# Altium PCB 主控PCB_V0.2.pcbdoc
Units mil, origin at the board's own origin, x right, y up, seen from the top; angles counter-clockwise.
Board outline 2286.79 x 1620 mil, 2 copper layers (Top Layer, Bottom Layer); 44 components, 39 nets, 171 pads, 174 vias.
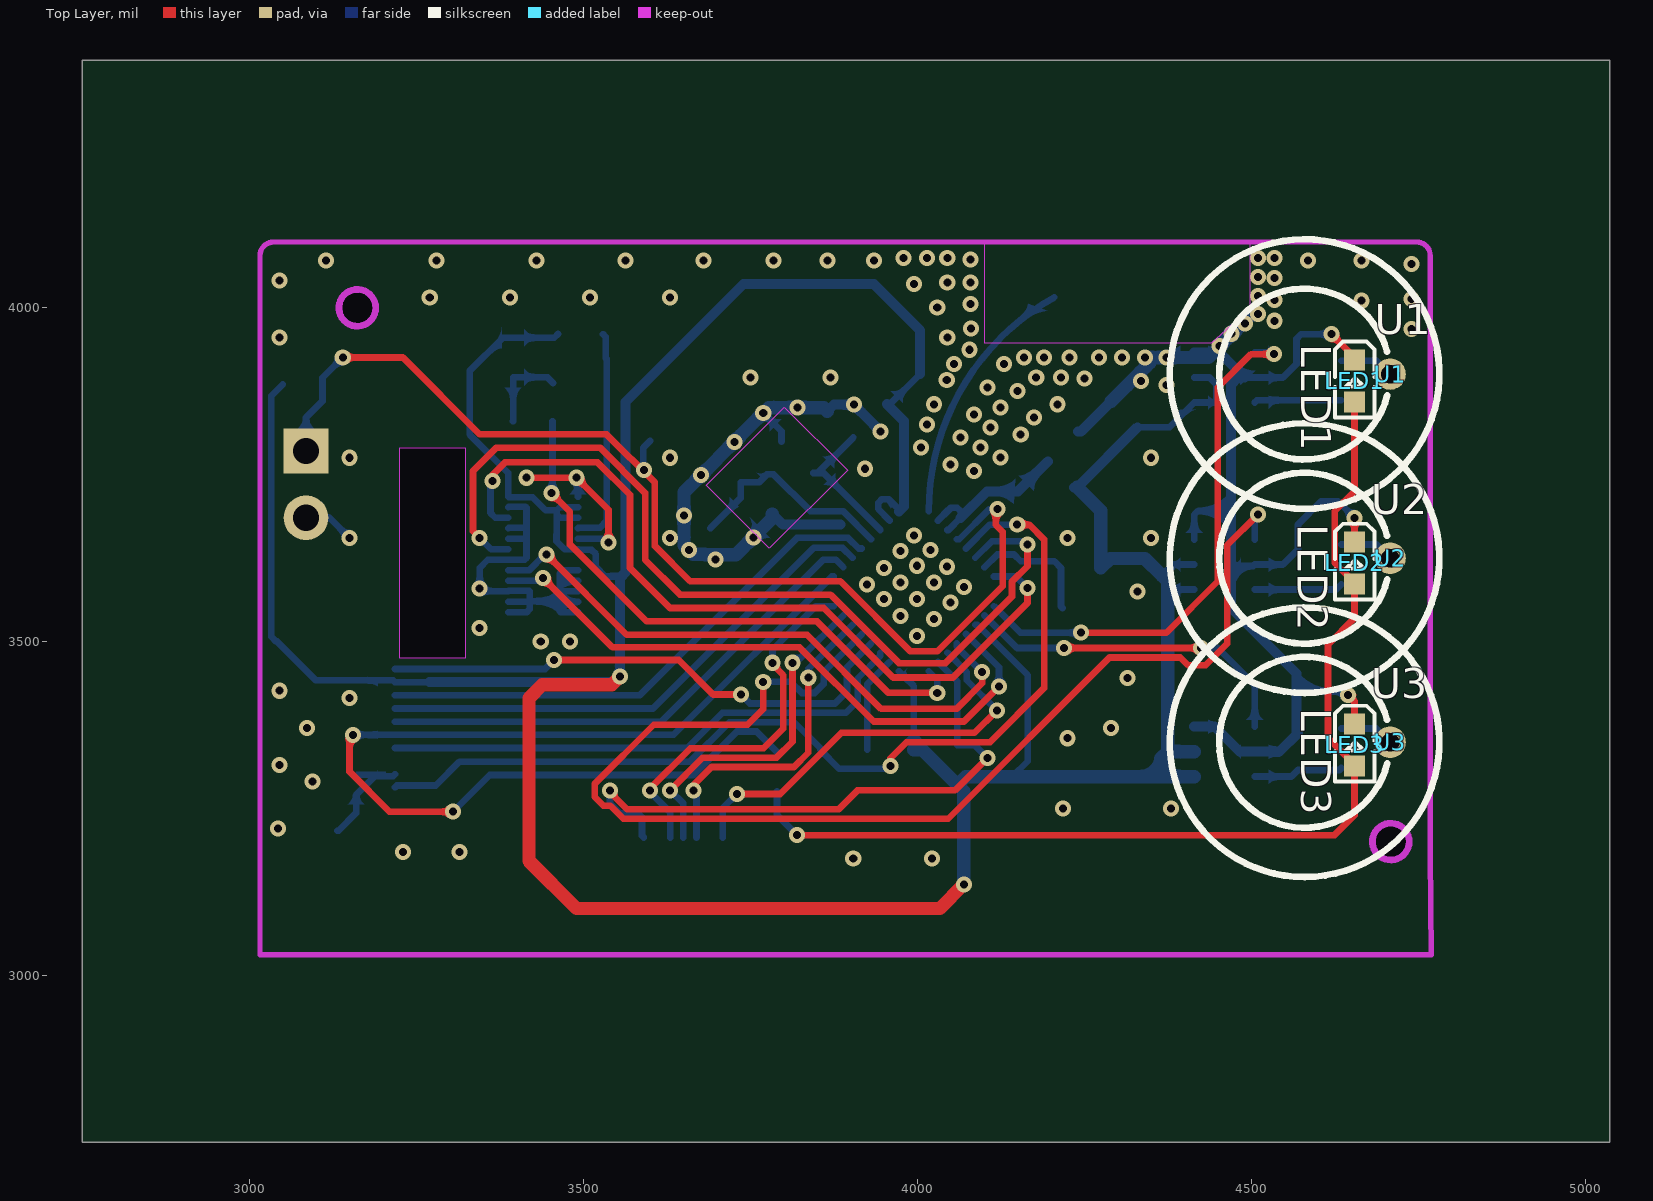
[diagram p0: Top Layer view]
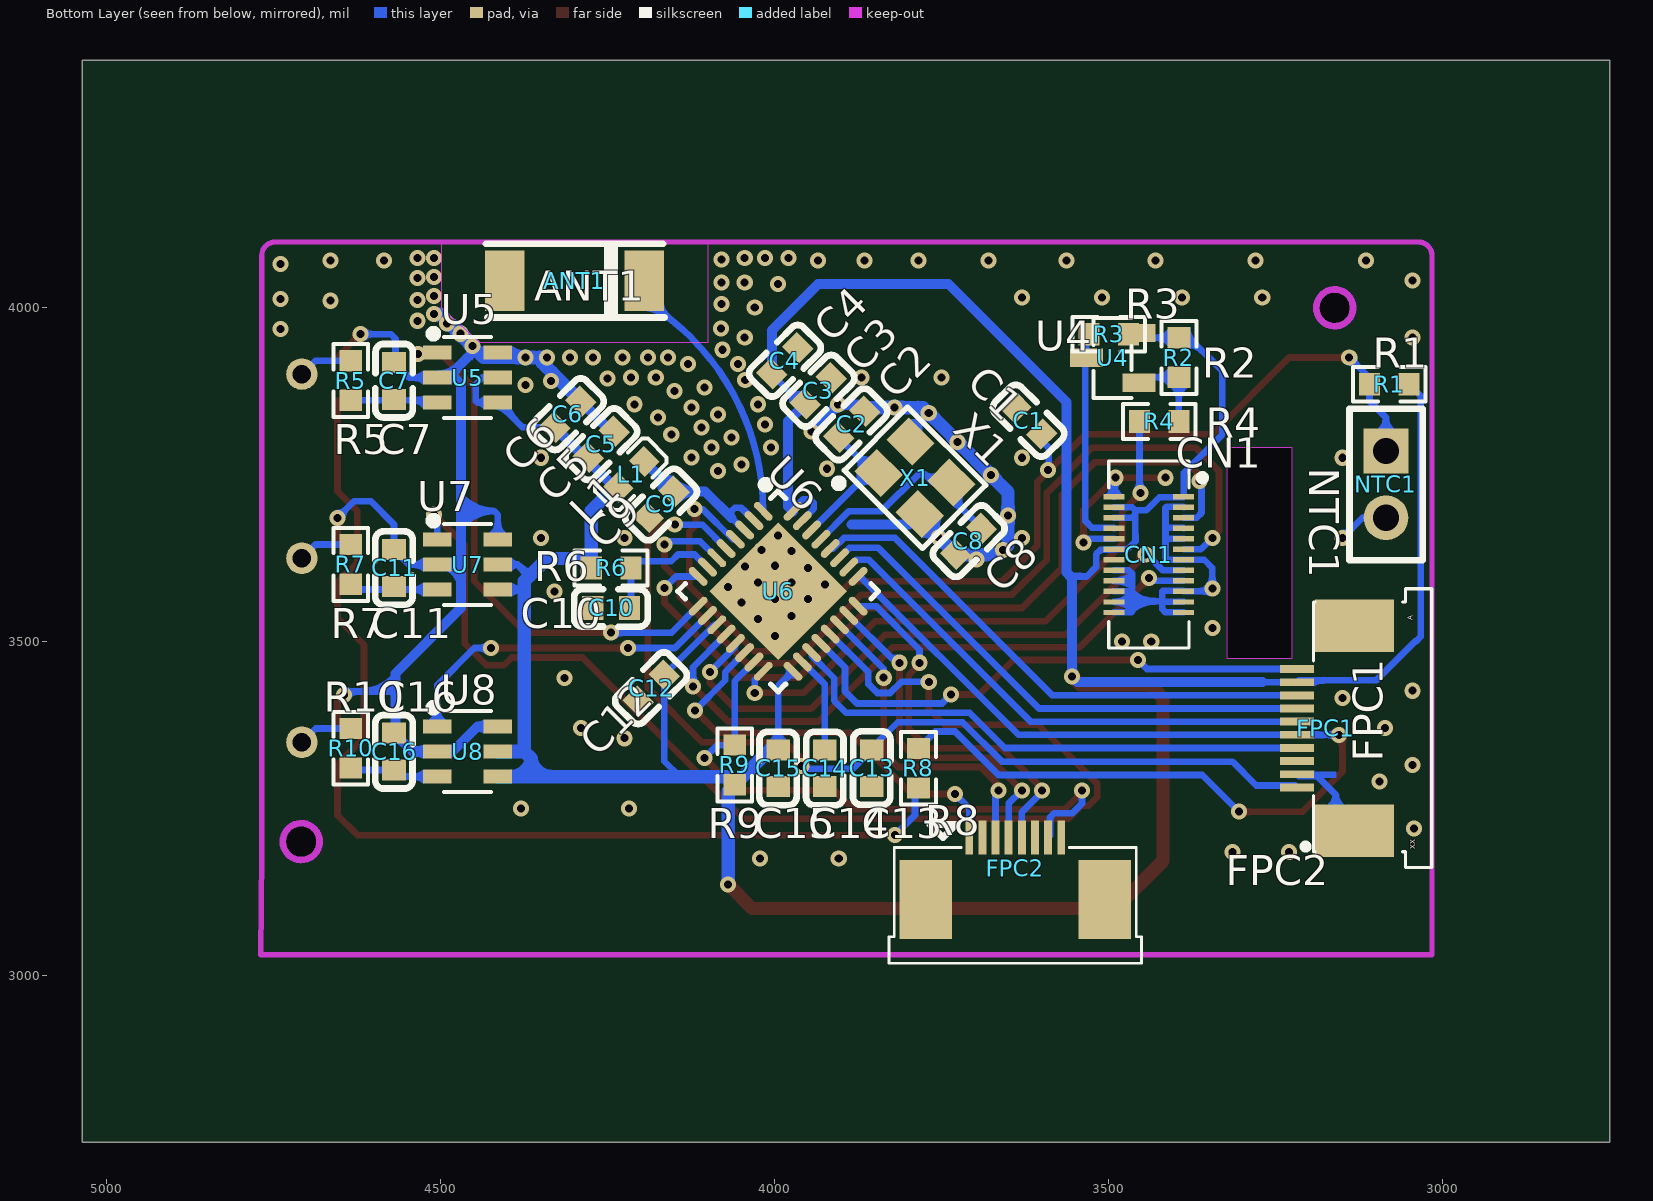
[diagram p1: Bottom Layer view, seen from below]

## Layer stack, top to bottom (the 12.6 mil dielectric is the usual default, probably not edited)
Top Layer: signal copper (thickness not stored)
Dielectric: dielectric 12.6, FR-4, Dk 4.8
Bottom Layer: signal copper (thickness not stored)

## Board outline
5036.79,2750 2750,2750 2750,4370 5036.79,4370
cut-out: 4736.57,3200.19 ccw(c4709.02,3199.82) 4681.46,3200.19 ccw(c4709.02,3200.56)
cut-out: 3189.33,3999.4 ccw(c3161.77,3999.4) 3134.21,3999.4 ccw(c3161.77,3999.4)
cut-out: 3225,3790 3323.43,3790 3323.43,3475.04 3225,3475.04

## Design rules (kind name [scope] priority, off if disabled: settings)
BoardOutlineClearance copperThickness1oz [All] p0: genericclearance=10 ignorepadtopadclearanceinfootprint=FALSE except(0: Arc-SplitContinuation Track-SplitContinuation SMDPad-SplitContinuation THPad-SplitContinuation Via-SplitContinuation Fill-SplitContinuation Poly-SplitContinuation Region-SplitContinuation Text-SplitContinuation; 6: Track-CutoutEdge SMDPad-CutoutEdge THPad-CutoutEdge Via-CutoutEdge Region-CutoutEdge; 11.8: Track-OutlineEdge SMDPad-OutlineEdge THPad-OutlineEdge Via-OutlineEdge Fill-OutlineEdge Region-OutlineEdge Poly-OutlineEdge Text-OutlineEdge Fill-CutoutEdge)
BoardOutlineClearance copperThickness2oz [All] p0: genericclearance=10 ignorepadtopadclearanceinfootprint=FALSE except(0: Arc-SplitContinuation Track-SplitContinuation SMDPad-SplitContinuation THPad-SplitContinuation Via-SplitContinuation Fill-SplitContinuation Poly-SplitContinuation Region-SplitContinuation Text-SplitContinuation; 6: Track-CutoutEdge SMDPad-CutoutEdge THPad-CutoutEdge Via-CutoutEdge Region-CutoutEdge; 11.8: Track-OutlineEdge SMDPad-OutlineEdge THPad-OutlineEdge Via-OutlineEdge Fill-OutlineEdge Region-OutlineEdge Poly-OutlineEdge Text-OutlineEdge Fill-CutoutEdge)
Clearance copperThickness1oz [(InNet('$1N1219') OR InNet('GND') OR InNet('3V3') OR InNet('$1N1185') OR InNet('$1N1981') OR InNet('$1N1223') OR InNet('$1N1184') OR InNet('CHIP_EN') OR InNet('VDD_SPI') OR InNet('$1N1977') OR InNet('$1N1980') OR InNet('GPIO0') OR InNet('GPIO6') OR InNet('GPIO7') OR InNet('GPIO2') OR InNet('K') OR InNet('GPIO3') OR InNet('ADC_VIN') OR InNet('ESP_TX') OR InNet('ESP_RX') OR InNet('GPIO13') OR InNet('GPIO12') OR InNet('DN1') OR InNet('DP1') OR InNet('$1N3691') OR InNet('$1N1982') OR InNet('$1N1983') OR InNet('$1N1984') OR InNet('GPIO9') OR InNet('$1N1544') OR InNet('BL') OR InNet('GPIO4') OR InNet('GPIO5') OR InNet('$1N7080') OR InNet('GPIO8') OR InNet('GPIO14') OR InNet('GPIO15') OR InNet('GPIO16') OR InNet('GPIO17'))] p1: gap=7 ignorepadtopadclearanceinfootprint=FALSE except(4: Track-Track; 6: Track-SMDPad SMDPad-SMDPad Track-THPad SMDPad-THPad THPad-THPad Track-Via SMDPad-Via THPad-Via Via-Via SMDPad-Fill THPad-Fill Via-Fill Fill-Fill Track-Region SMDPad-Region THPad-Region Via-Region Region-Region Track-Poly SMDPad-Poly THPad-Poly Via-Poly Fill-Poly Region-Poly Poly-Poly Track-Text SMDPad-Text THPad-Text Via-Text Fill-Text Region-Text Poly-Text Text-Text; 6.9: Track-Hole SMDPad-Hole THPad-Hole Via-Hole Fill-Hole Region-Hole Poly-Hole Text-Hole Sheet-Hole; 11.8: Track-Fill Fill-Region Track-Sheet SMDPad-Sheet THPad-Sheet Via-Sheet Fill-Sheet Region-Sheet Poly-Sheet Text-Sheet)
Clearance copperThickness2oz [All] p1: gap=7 ignorepadtopadclearanceinfootprint=FALSE except(6: Track-SMDPad SMDPad-SMDPad Track-THPad SMDPad-THPad THPad-THPad Track-Via SMDPad-Via THPad-Via Via-Via SMDPad-Fill THPad-Fill Via-Fill Fill-Fill Track-Region SMDPad-Region THPad-Region Via-Region Region-Region Track-Poly SMDPad-Poly THPad-Poly Via-Poly Fill-Poly Region-Poly Poly-Poly Track-Text SMDPad-Text THPad-Text Via-Text Fill-Text Region-Text Poly-Text Text-Text; 6.9: Track-Hole SMDPad-Hole THPad-Hole Via-Hole Fill-Hole Region-Hole Poly-Hole Text-Hole Sheet-Hole; 8: Track-Track; 11.8: Track-Fill Fill-Region Track-Sheet SMDPad-Sheet THPad-Sheet Via-Sheet Fill-Sheet Region-Sheet Poly-Sheet Text-Sheet)
DiffPairsRouting differentialPair [All] p1: maxuncoupledlength=10 minlimit=6 maxlimit=6 mostfreqgap=6 toplayer_minwidth=5 toplayer_prefwidth=10 toplayer_maxwidth=100 bottomlayer_minwidth=5 bottomlayer_prefwidth=10 bottomlayer_maxwidth=100
PasteMaskExpansion pasteMaskExpansion [All] p1: expansion=0
PlaneConnect innerPlane [All] p1: planeconnectstyle=Relief reliefexpansion=20 reliefentries=4 reliefconductorwidth=10 reliefairgap=10
PolygonConnect copperRegion [All] p1: connectstyle=Relief reliefentries=4 reliefconductorwidth=10 polygonreliefangle="90 Angle" airgapwidth=10
RoutingVias viaSize [All] p1: viastyle="Through Hole" holewidth=12.0078 minholewidth=11.811 maxholewidth=248.0314 width=24.0158 minwidth=19.685 maxwidth=393.7008
SolderMaskExpansion solderMaskExpansion [All] p1: useseparateexpansions=TRUE expansion=2 expansionbottom=2
Width copperThickness1oz [All] p1: maxlimit=100 minlimit=5 preferedwidth=10
Width copperThickness2oz [All] p1: maxlimit=100 minlimit=8 preferedwidth=10

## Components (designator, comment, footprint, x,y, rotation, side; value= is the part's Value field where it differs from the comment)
ANT1 "CA-C03" ANT-SMD_CA-C03 4300,4040 r180 bottom
C1 "CGA0603X7R104K500JT" C0603 3620,3830 r225 bottom
C2 "CC0603KRNPO9BN100" C0603 3885,3825 r135 bottom
C3 "CC0603KRX7R9BB104" C0603 3935,3875 r315 bottom
C4 "CL10A106KP8NNNC" C0603 3985,3920 r315 bottom
C5 "CL10A105KA8NNNC" C0603 4260,3795 r315 bottom
C6 "CL10A106KP8NNNC" C0603 4310,3840 r315 bottom
C7 "CC0603JRNPO9BN150" C0603 4570,3890 r270 bottom
C8 "CC0603FRNPO9BN100" C0603 3710,3650 r315 bottom
C9 "CC0603KRX7R9BB104" C0603 4170,3705 r135 bottom
C10 "CL10A105KA8NNNC" C0603 4245,3550 r180 bottom
C11 "CC0603JRNPO9BN150" C0603 4570,3610 r90 bottom
C12 "CC0603KRX7R9BB104" C0603 4185,3430 r135 bottom
C13 "CGA0603X7R104K500JT" C0603 3855,3310 r270 bottom
C14 "CL10A106KP8NNNC" C0603 3925,3310 r90 bottom
C15 "CC0603KRX7R9BB104" C0603 3995,3310 r90 bottom
C16 "CC0603JRNPO9BN150" C0603 4570,3335 r90 bottom
CN1 "DF37NC-24DS-0.4V(51)" CONN-SMD_DF37NC-24DS-0.4V-51 3440,3630 r270 bottom locked
FPC1 "F0501-T-10-20T-R" FPC-SMD_F0501-T-10-20T-R 3175,3370 r90 bottom locked
FPC2 "F0501-T-08-20T-R" FPC-SMD_8P-P0.50_L4.4-W9.6 3640,3160 r180 bottom
L1 "SDCL1608C2N0STDF" l0603 4215,3750 r135 bottom
LED1 "LTST-C193TBKT-5A" LED0603-RD 4655,3890 r270 top
LED2 "LTST-C193TBKT-5A" LED0603-RD 4655,3617.5 r270 top
LED3 "LTST-C193TBKT-5A" LED0603-RD 4655,3345 r270 top
NTC1 "HDR-F_2.54_1x2P" HDR-TH_2P-P2.54-V-F 3085,3735 r270 bottom
R1 "0603WAF1002T5E" R0603 3080,3885 r180 bottom
R2 "Res_0402" R0603 3395,3925 r270 bottom
R3 "Res_0402" R0603 3500,3960 r0 bottom
R4 "0603WAF1001T5E" R0603 3424.33,3829.34 r180 bottom
R5 "0603WAF1001T5E" R0603 4635,3890.56 r270 bottom
R6 "0603WAF1002T5E" R0603 4245,3610 r180 bottom
R7 "0603WAF1001T5E" R0603 4635,3615.28 r270 bottom
R8 "0603WAF3300T5E" R0603 3785,3310 r270 bottom
R9 "0603WAF1002T5E" R0603 4060,3315 r90 bottom
R10 "0603WAF1001T5E" R0603 4635,3340 r270 bottom
U1 "F10-10-6.5-0.4P" TH_F10-10-6.5-0.4P 4707.91,3900.16 r0 top
U2 "F10-10-6.5-0.4P" TH_F10-10-6.5-0.4P 4707.91,3624.57 r0 top
U3 "F10-10-6.5-0.4P" TH_F10-10-6.5-0.4P 4707.91,3348.98 r0 top
U4 "AO3401_1" SOT-23-3_L2.9-W1.3-P1.90-LS2.4-BR 3494.2,3924.34 r180 bottom
U5 "JL423B" SOT-23-6_L2.9-W1.6-P0.95-LS2.8-BL-2 4460,3895 r270 bottom
U6 "ESP32-C3FN4" QFN-32_L5.0-W5.0-P0.50-BL-EP3.7 3995,3575 r315 bottom locked
U7 "JL423B" SOT-23-6_L2.9-W1.6-P0.95-LS2.8-BL-2 4460,3615 r270 bottom
U8 "JL423B" SOT-23-6_L2.9-W1.6-P0.95-LS2.8-BL-2 4460,3335 r270 bottom
X1 "X322540MPB4SI" OSC-SMD_4P-L3.2-W2.5-BL_SIT8008BI 3790,3745 r225 bottom

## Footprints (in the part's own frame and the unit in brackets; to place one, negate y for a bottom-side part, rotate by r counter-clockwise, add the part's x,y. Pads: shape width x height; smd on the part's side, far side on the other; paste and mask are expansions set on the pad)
ANT-SMD_CA-C03 [mm]
  rect 1.5x2.3 smd: 1(-2.65,0) 2(2.65,0)
  silkscreen extent -3.37,-1.4 3.43,1.4
C0603 [mm]
  rect 0.8x0.9 smd: 1(-0.7,0) 2(0.7,0)
  silkscreen extent -1.41,-0.71 1.39,0.72
CONN-SMD_DF37NC-24DS-0.4V-51 [mm]
  rect 0.2x0.8 smd: 1(-2.2,1.325) 2(-2.2,-1.325) 3(-1.8,1.325) 4(-1.8,-1.325) 5(-1.4,1.325) 6(-1.4,-1.325) 7(-1,1.325) 8(-1,-1.325) 9(-0.6,1.325) 10(-0.6,-1.325) 11(-0.2,1.325) 12(-0.2,-1.325) 13(0.2,1.325) 14(0.2,-1.325) 15(0.6,1.325) 16(0.6,-1.325) 17(1,1.325) 18(1,-1.325) 19(1.4,1.325) 20(1.4,-1.325) 21(1.8,1.325) 22(1.8,-1.325) 23(2.2,1.325) 24(2.2,-1.325)
  silkscreen extent -3.56,-1.52 3.56,2.16
FPC-SMD_8P-P0.50_L4.4-W9.6 [mm]
  rect 2x3 smd: 0(-3.4,-1.175) 0(3.4,-1.175)
  rect 0.3x1.3 smd: 1(-1.75,1.175) 2(-1.25,1.175) 3(-0.75,1.175) 4(-0.25,1.175) 5(0.25,1.175) 6(0.75,1.175) 7(1.25,1.175) 8(1.75,1.175)
  silkscreen extent -4.8,-3.6 4.8,1.68
FPC-SMD_F0501-T-10-20T-R [mm]
  rect 0.3x1.3 smd: 1(-2.25,1.097) 2(-1.75,1.097) 3(-1.25,1.097) 4(-0.75,1.097) 5(-0.25,1.097) 6(0.25,1.097) 7(0.75,1.097) 8(1.25,1.097) 9(1.75,1.097) 10(2.25,1.097)
  rect 2x3 smd: 11(3.9,-1.097) 12(-3.9,-1.097)
  silkscreen extent -5.3,-4.03 5.3,0.87
HDR-TH_2P-P2.54-V-F [mm]
  rect 1.7x1.7 hole 1: 1(-1.27,0)
  round 1.7 hole 1: 2(1.27,0)
  silkscreen extent -2.88,-1.39 2.88,1.4
l0603 [mm]
  rect 0.8x0.864 smd: 1(-0.7,0) 2(0.7,0)
  silkscreen extent -1.42,-0.65 1.41,0.67
LED0603-RD [mm]
  rect 0.8x0.8 smd: 1(-0.799,0) 2(0.799,0)
  silkscreen extent -1.49,-0.75 1.39,0.76
OSC-SMD_4P-L3.2-W2.5-BL_SIT8008BI [mm]
  rect 1.4x1.2 smd: 1(-1.1,-0.85) 2(1.1,-0.85) 3(1.1,0.85) 4(-1.1,0.85)
  silkscreen extent -2.1,-2.35 2.1,1.7
QFN-32_L5.0-W5.0-P0.50-BL-EP3.7 [mm]
  oval 0.28x0.9 smd: 1(-1.75,-2.55) 2(-1.25,-2.55) 3(-0.749,-2.55) 4(-0.249,-2.55) 5(0.249,-2.55) 6(0.749,-2.55) 7(1.25,-2.55) 8(1.75,-2.55) 17(1.75,2.55) 18(1.25,2.55) 19(0.749,2.55) 20(0.249,2.55) 21(-0.249,2.55) 22(-0.749,2.55) 23(-1.25,2.55) 24(-1.75,2.55)
  oval 0.9x0.28 smd: 9(2.55,-1.75) 10(2.55,-1.25) 11(2.55,-0.749) 12(2.55,-0.249) 13(2.55,0.249) 14(2.55,0.749) 15(2.55,1.25) 16(2.55,1.75) 25(-2.55,1.75) 26(-2.55,1.25) 27(-2.55,0.749) 28(-2.55,0.249) 29(-2.55,-0.249) 30(-2.55,-0.749) 31(-2.55,-1.25) 32(-2.55,-1.75)
  rect 3.7x3.7 smd: 33(0,0)
  silkscreen extent -2.7,-3.35 2.7,2.7
R0603 [mil]
  rect 31.75x34.02 smd: 1(-29.66,0) 2(29.66,0)
  silkscreen extent -55,-26 55,26
SOT-23-3_L2.9-W1.3-P1.90-LS2.4-BR [mm]
  rect 1.25x0.7 smd: 1(1,-0.95) 2(1,0.95) 3(-1,0)
  silkscreen extent -0.73,-1.53 0.73,1.53
SOT-23-6_L2.9-W1.6-P0.95-LS2.8-BL-2 [mil]
  rect 20.95x42.2 smd: 1(-37.4,-45.24) 2(0,-45.24) 3(37.4,-45.24) 4(37.4,45.24) 5(0,45.24) 6(-37.4,45.24)
  silkscreen extent -72,-57 61,35
TH_F10-10-6.5-0.4P [mm]
  round 1.2 hole 0.7: 1(0,0)
  silkscreen extent -8.37,-5.13 1.87,5.13

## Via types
v1: diameter 24.02, hole 12.01, Top Layer to Bottom Layer, 174 vias

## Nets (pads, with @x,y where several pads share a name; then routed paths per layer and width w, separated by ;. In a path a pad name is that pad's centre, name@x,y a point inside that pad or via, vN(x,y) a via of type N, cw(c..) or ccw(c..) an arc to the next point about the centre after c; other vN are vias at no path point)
3V3: C3.2 C4.2 C5.2 C6.2 C12.2 C15.2 CN1.1 CN1.4 CN1.6 CN1.12 FPC1.9 L1.1 R1.2 R2.1 R3.1 R6.1 R9.1 U4.2 U5.4 U5.5 U6.11 U6.17 U6.31 U6.32 U7.4 U7.5 U8.4 U8.5 | length 6076
  Top Layer w20: v1(3555,3447.21) 3542.79,3435 3438.82,3435 3418.82,3415 3418.82,3171.18 3490,3100 4033.67,3100 v1(4069.85,3136.18)
  Bottom Layer w10: 3032.92,3867.58 R1.2 ; 3032.93,3867.58 3032.93,3507.07 3040,3500 3041.41,3500 3099.71,3441.7 3215.38,3441.7 FPC1.9 3270,3438.89 ; R3.1@3462.13,3960.14 3456.64,3954.66 3379.66,3954.66 3330,3905 3330,3810 3387.84,3752.16 CN1.1 3388.66,3715.79 3424.21,3715.79 3443.75,3696.25 3460.39,3696.25 ; CN1.6 3465,3685.11 3460.39,3689.73 ; CN1.4 3465,3700.86 3460.39,3696.25 ; 3557.5,3597.5 3532.54,3597.5 3518.9,3611.14 3518.9,3630.61 3512.46,3637.05 3492.99,3637.05 CN1.12 3472.12,3637.88 3460,3650 3460,3660 3460.39,3660.39 3460.39,3689.73 ; C3.2 3959.49,3855.51 C4.2 ; U6.31 3958.8,3681.2 3941.59,3698.41 3941.59,3707.45 3947.07,3712.93 3957.07,3712.93 3972.73,3697.27 U6.32 ; U6.17 3995,3433.01 C15.2@3995,3340 ; U6.11 4090.13,3524.87 C12.2 4165.51,3320.51 4142.6,3297.6 ; C6.2 4377.67,3820.51 U5.4 4445.2,3857.6 4447.6,3860 4447.6,3885 4437.6,3895 U5.5 ; 4366.57,3598.43 4368.43,3598.43 4385,3615 U7.5 ; 4375,3577.05 4375.55,3577.6 U7.4 ; 3460.39,3689.73 3460.39,3696.25
  Bottom Layer w15: 3270,3438.89 3546.69,3438.89 v1(3555,3447.21) 3555,3595 3557.5,3597.5 3563.36,3603.36 3563.36,3858.36 3740,4035 3935,4035 4004.49,3965.51 C4.2 ; C3.2 3980,3830 3980,3701.99 U6.32 ; C15.2 C15.2@3995,3340 ; L1.1 4239.49,3730.52 C6.2
  Bottom Layer w20: C15.2 4007.78,3337.56 R9.1 ; v1(4069.85,3136.18) 4069.85,3275.49 R9.1 ; L1.1@4239.49,3730.52 4274.66,3695.35 R6.1 4288.8,3624.14 4340.86,3624.14 4366.57,3598.43 4375,3590 4375,3577.05 4375,3335 ; U8.4 4364.65,3297.6 ; U8.5 4375,3335 ; R9.1 4060.34,3285.34 4072.6,3297.6 4142.6,3297.6 4364.65,3297.6 ; 4364.65,3297.6 4364.65,3324.65 4375,3335
$1N1184: C8.1 U6.29 X1.3 | length 327.7
  Bottom Layer w10: C8.1 3735.71,3714.69 X1.3 3763.04,3738.04 3775,3750 3785,3750 3840,3695 3888.86,3695 U6.29
$1N1185: C2.1 U6.30 X1.1 | length 211.6
  Bottom Layer w10: X1.1 X1.1@3850.94,3751.96 ; C2.1 X1.1@3850.94,3751.96 ; U6.30 3859.76,3751.96 X1.1@3850.94,3751.96
$1N1219: ANT1.2 U6.1 | length 389.2
  Bottom Layer w10: U6.1 cw(c4384.36,3694.71) ANT1.2@4205,4015
$1N1223: C9.2 L1.2 U6.2 U6.3 | length 246.7
  Bottom Layer w10: U6.2 4050.42,3700 4060,3700 4065,3695 4065,3685 4046.85,3666.85 U6.3
  Bottom Layer w15: 4065,3685 4104.49,3724.49 C9.2 L1.2
$1N1544: R2.2 R4.2 U4.1 | length 129.4
  Bottom Layer w10: R4.2 3395,3829.68 R2.2 3446.43,3895.34 U4.1
$1N1977: C7.2 R5.2 U5.3 | length 131.1
  Bottom Layer w10: U5.3 4508.54,3860.9 R5.2
$1N1980: C16.1 R10.2 U8.3 | length 135
  Bottom Layer w10: U8.3 4560.16,3297.6 C16.1 4632.1,3307.44 R10.2
$1N1981: C11.1 R7.2 U7.3 | length 133.1
  Bottom Layer w10: U7.3 4626.98,3577.6 R7.2
$1N1982: R5.1 U1.1 | length 81.2
  Bottom Layer w10: R5.1 4687.85,3920.22 U1.1
$1N1983: R10.1 U3.1 | length 81.5
  Bottom Layer w10: R10.1 4687.23,3369.66 U3.1
$1N1984: R7.1 U2.1 | length 81.4
  Bottom Layer w10: R7.1 4687.54,3644.94 U2.1
$1N3691: LED1.2 LED2.2 LED3.2 R8.2 | length 1603.3
  Top Layer w10: v1(3820,3210) 4625,3210 4654.8,3239.8 4654.8,3315.5 4615,3355.3 4615,3495 4654.8,3534.8 4654.8,3588 4625,3617.8 4625,3695 4654.8,3724.8 LED1.2@4654.8,3860.5
  Bottom Layer w10: R8.2@3790,3275.34 3790,3240 v1(3820,3210)
$1N7080: FPC1.3
ADC_VIN: C13.1 FPC1.1 U6.5 | length 1462.9
  Top Layer w10: v1(3960,3313.65) 3960,3325 3983.98,3348.98 4108.98,3348.98 4190,3430 4190,3652.52 4167.77,3674.75 v1(4149.75,3674.75)
  Bottom Layer w10: FPC1.1 3220.98,3284.22 3279.22,3284.22 3315,3320 3660,3320 3719.02,3379.02 3815.98,3379.02 3855,3340 C13.1 3883.39,3309.17 3955.52,3309.17 v1(3960,3313.65) ; U6.5 4108.61,3674.75 v1(4149.75,3674.75)
BL: R4.1 U6.16 | length 876
  Top Layer w10: v1(3452.29,3721.87) 3480,3694.15 3480,3645 3595,3530 3850,3530 3957.01,3422.99 v1(4030,3422.99)
  Bottom Layer w10: v1(3452.29,3721.87) 3453.99,3723.57 R4.1 ; U6.16 4030,3442.56 v1(4030,3422.99)
CHIP_EN: C10.2 R6.2 U6.7 | length 191.5
  Bottom Layer w10: U6.7 4101.2,3611.2 4120,3630 4145,3630 4155,3620 4205.34,3620 R6.2 4215.34,3552.1 C10.2
DN1: FPC1.5 R8.1 U6.25 | length 1602.8
  Top Layer w10: v1(3155,3360) 3150,3355 3150,3305 3210,3245 v1(3305,3245)
  Bottom Layer w10: v1(3155,3360) 3218.02,3360 FPC1.5 3635.16,3360.16 3872.27,3597.27 U6.25 ; v1(3305,3245) 3360,3300 3665,3300 3730,3365 3759.66,3365 R8.1@3790,3334.66
DP1: FPC1.6 U6.26 | length 776.1
  Bottom Layer w10: FPC1.6 3617.27,3379.84 3859.82,3622.4 3878.02,3622.4 U6.26
ESP_RX: FPC1.7 U6.27 | length 790.7
  Bottom Layer w10: FPC1.7 3604.53,3399.53 3845,3640 3888.28,3640 U6.27
ESP_TX: FPC1.8 U6.28 | length 803.2
  Bottom Layer w10: FPC1.8 3584.22,3419.22 3820,3655 3896.61,3655 3912.55,3639.06 U6.28
GND: C1.1 C2.2 C3.1 C4.1 C5.1 C6.1 C7.1 C8.2 C9.1 C10.1 C11.2 C12.1 C13.2 C14.1 C15.1 C16.2 CN1.2 CN1.3 CN1.7 CN1.9 CN1.10 CN1.13 CN1.16 CN1.18 CN1.19 CN1.20 CN1.21 CN1.22 CN1.23 CN1.24 FPC1.2 FPC1.11 FPC1.12 FPC2.0 LED1.1 LED2.1 LED3.1 NTC1.2 U5.2 U5.6 U6.33 U7.2 U7.6 U8.2 U8.6 X1.2 X1.4 | length 3883.7
  Top Layer w10: v1(3415,3745) v1(3490,3745) 3537.87,3697.13 v1(3537.87,3647.85) ; v1(4620,3960) 4654.6,3925.4 LED1.1@4654.6,3923.5 ; v1(4645,3420) 4654.6,3410.4 LED3.1@4654.6,3378.5 ; LED2.1@4654.6,3651 v1(4654.6,3685)
  Top Layer w20: v1(4225,3655) v1@4225.08,3654.92
  Bottom Layer w10: NTC1.2 3120.12,3685 v1(3150.2,3654.92) ; FPC1.12 3133.53,3216.45 3160,3242.93 3160,3270.27 3188.04,3298.3 3215.38,3298.3 FPC1.2 ; CN1.23 3415,3543.39 3419.87,3548.25 3419.87,3560.06 ; CN1.21 3418.94,3559.14 3419.87,3560.06 ; CN1.9 3413.62,3653.62 3415,3655 ; CN1.7 3388.65,3670.19 3414.81,3670.19 3415,3670 ; CN1.3 3388.66,3701.69 3413.31,3701.69 3415,3700 3415,3670 ; 3419.93,3560 3464.94,3560 ; 3464.94,3545.06 3464.94,3560 ; 3464.94,3574.89 3464.94,3560 ; 3465,3545 3466.61,3543.39 CN1.24 ; 3465.2,3580.1 3465.2,3601.58 3470,3606.38 CN1.16 ; 3465.86,3559.14 CN1.22 ; 3465.84,3590.64 CN1.18 ; 3470,3574.89 CN1.20 ; v1(3490,3745) 3492.16,3742.84 CN1.2 ; CN1.10 3532.1,3653.62 v1(3537.87,3647.85) ; v1(3769.52,3842.02) 3796.96,3814.58 X1.4 ; U7.6 4414.76,3689.76 4420,3695 4467.58,3695 4470,3692.58 ; 4470,3620 4477.07,3612.93 4503.17,3612.93 U7.2 4547.44,3615 C11.2 4570,3675 4605,3710 4629.6,3710 v1(4654.6,3685) ; U5.2@4490,3895 U5.2 4547.44,3895 C7.1 4567.93,3919.63 4567.93,3952.93 4575,3960 v1(4620,3960) ; 4567.93,3417.93 4575,3425 4640,3425 v1(4645,3420) ; 3415,3655 3415,3670 ; 3415,3655 3415,3625 3412.12,3622.12 CN1.13 3357.12,3622.12 3345,3610 v1(3345,3579.03) 3349.14,3574.89 CN1.19 3388.66,3575.71 3419.15,3575.71 3419.87,3575 3419.87,3560.06
  Bottom Layer w15: X1.2 3798.75,3675 3885,3675 ; C2.2 3875.51,3854.49 v1(3905.21,3854.49) 3905.21,3854.29 v1(3945.06,3814.44) ; C5.1 4245.51,3814.49 C6.1 ; U8.6 4445,3372.4 4482.4,3335 U8.2 4542.44,3335 C16.2 4567.93,3364.63 4567.93,3417.93 4567.93,3452.07 4470,3550 4470,3620 4470,3692.58 4470,3885 4480,3895 4490,3895 4452.6,3932.4 4442.98,3932.4 U5.6
  Bottom Layer w20: X1.2 3783.04,3684.06 v1(3754.62,3655.64) C8.2 3728.82,3629.84 3682.5,3629.84 3681.83,3630.51 3664.49,3630.51 3650.86,3644.14 v1(3650.86,3688.7) 3650.86,3723.36 v1(3676.42,3748.92) v1(3726.15,3798.65) v1(3769.52,3842.02) 3777.5,3850 v1(3820.55,3850) 3860,3850 C2.2 ; C6.1 v1@4348.43,3917.4 ; v1(4340.83,3925) v1(4373.35,3925) 4435.58,3925 4442.98,3932.4 v1(4452.6,3942.02) 4500.58,3990 v1(4510,3990)
  other v1: 3904.26,3175 4021.85,3175 3230,3185 3315,3185 3043.21,3219.55 4218.54,3250 4380,3250 3095,3290 3045,3315 4225,3355 3086.42,3370 4290,3370 3150.2,3414.92 3045,3426.12 4315,3445 3436.41,3500 3480,3500 4000,3508.24 3345,3520 4025,3533.24 3974.91,3538.24 4050,3558.24 3950,3563.24 3999.91,3563.24 4330,3575 4070,3581.76 3925,3585 3975,3588.24 4024.91,3588.24 3950,3610 4044.91,3611.76 4000,3613.24 3698.05,3622.44 3975,3635 3658.27,3636.73 4020,3636.76 3630.2,3654.92 4350.2,3654.92 3995,3658.52 4085,3755 3921.79,3758.47 4050,3765 3150.2,3774.92 3630.2,3774.92 4125,3775 4350.2,3774.92 4005.49,3789.95 4095,3790 4065,3805 4155,3810 4110,3820 4015,3825 4175,3835 4085,3840 4125,3850 4025,3855 4210,3855 4150,3875 4105,3880 4373.35,3883.83 4335,3890 4044.23,3891.07 4250.33,3893.68 3750.2,3894.92 3870.2,3894.92 4178.21,3895 4215,3895 4055,3915 4130,3915 4160,3925 4189.99,3925 4227.7,3925 4272.01,3925 4306.89,3925 4078.34,3936.61 3045,3955 4045,3955 4470.32,3960.6 4080.49,3968.29 4740,3967.89 4490.56,3975.86 4535,3980.01 4030,4000 4080,4005 4665,4010 4535,4011.31 4740,4012.65 3270.2,4014.92 3390.2,4014.92 3510.2,4014.92 3630.2,4014.92 4510,4017.02 3995,4035 4080,4037.23 4045,4037.56 3045,4040 4535,4044.12 4510,4045.3 4740,4065 3115,4070 3280,4070 3430,4070 3563.06,4070 3680,4070 3785,4070 3865.68,4070 3935,4070 4585,4070 4665,4070 4080,4071.64 3979.28,4074 4015,4074 4045,4074 4510,4074 4535,4074
GPIO0: C1.2 NTC1.1 R1.1 U6.4 | length 1679.1
  Top Layer w10: v1(3140,3925) 3230,3925 3345,3810 3535,3810 3607.21,3737.79 3607.21,3642.79 3660,3590 3885,3590 3990,3485 4030,3485 4127.99,3582.99 4127.99,3663.99 4117.5,3674.48 4117.5,3695.49 v1(4120,3697.99)
  Bottom Layer w10: NTC1.1 3085,3835 3109.66,3859.66 R1.1 3109.66,3894.66 v1(3140,3925) ; v1@3590,3755 3590,3790 C1.2@3600.51,3800.51 ; U6.4 4062.92,3652.92 4107.99,3697.99 v1(4120,3697.99)
  other v1: 3591.26,3756.26
GPIO2: CN1.11 U6.6 | length 1387
  Top Layer w10: v1(3345,3655) 3335,3665 3335,3755 3370,3790 3525,3790 3592.75,3722.25 3592.75,3622.25 3645,3570 3870,3570 3972.5,3467.5 4042.5,3467.5 4142.01,3567.01 4142.01,3589.52 4165,3612.52 v1(4165,3645)
  Bottom Layer w10: v1(3345,3655) 3362.12,3637.88 CN1.11 ; U6.6 4111.72,3650 4160,3650 v1(4165,3645)
GPIO3: CN1.5 U6.8 | length 1220.1
  Top Layer w10: v1(3364.09,3740) 3364.09,3749.09 3382.99,3767.99 3521.53,3767.99 3570,3719.52 3570,3610 3630,3550 3860,3550 3964.02,3445.98 4053.47,3445.98 4165,3557.52 v1(4165,3580)
  Bottom Layer w10: v1(3364.09,3740) 3361.1,3737.01 3361.1,3692.38 3368.37,3685.11 CN1.5 ; U6.8 4147.73,3597.27 v1(4165,3580)
GPIO4: U5.1 U6.9 | length 808.7
  Top Layer w10: v1(4245,3512.99) 4372.99,3512.99 4450,3590 4450,3880 4500,3930 v1(4534.29,3930)
  Bottom Layer w10: U6.9 4154.45,3512.99 v1(4245,3512.99) ; U5.1 4531.89,3932.4 v1(4534.29,3930)
GPIO5: U6.10 U8.1 | length 509.9
  Top Layer w10: v1(4220,3490) v1(4425,3490)
  Bottom Layer w10: U6.10 4149.58,3490 v1(4220,3490) ; v1(4425,3490) 4450,3490 4505.24,3434.76 U8.1
GPIO6: CN1.17 U6.12 | length 946.2
  Top Layer w10: v1(3440,3595) 3544.02,3490.98 3824.02,3490.98 3935,3380 4070,3380 v1(4122.5,3432.5)
  Bottom Layer w10: CN1.17 3435.64,3590.64 v1(3440,3595) ; U6.12 4122.5,3461.36 v1(4122.5,3432.5)
GPIO7: CN1.15 U6.13 | length 906.4
  Top Layer w10: v1(3445,3630) 3565,3510 3835,3510 3945.98,3399.02 4059.02,3399.02 4097.24,3437.24 v1(4097.24,3454.1)
  Bottom Layer w10: CN1.15 3418.86,3606.38 3442.48,3630 v1(3445,3630) ; U6.13 4059.06,3492.55 4070.26,3481.35 4070.26,3481.08 v1(4097.24,3454.1)
GPIO8: FPC2.1 U6.14 | length 632.2
  Top Layer w10: v1(3730,3271.5) 3794.88,3271.5 3886.37,3362.99 4085.48,3362.99 v1(4119.23,3396.75)
  Bottom Layer w10: FPC2.1 3708.89,3250.4 v1(3730,3271.5) ; U6.14 4074.25,3454.03 4074.25,3441.73 v1(4119.23,3396.75)
GPIO9: FPC2.7 R9.2 U6.15 | length 907.4
  Top Layer w10: v1(3540,3277.01) 3547.01,3270 3547.01,3267.48 3565.98,3248.51 3882.17,3248.51 3910.66,3277.01 4056.42,3277.01 v1(4105,3325.59)
  Bottom Layer w10: v1(3540,3277.01) 3540,3257.05 3554.21,3242.83 3581.56,3242.83 3587.99,3236.4 3587.99,3209.05 FPC2.7 ; U6.15 4060,3440.42 R9.2 4085.93,3344.66 v1(4105,3325.59)
GPIO12: FPC1.4 U6.19 | length 808.2
  Bottom Layer w10: FPC1.4 3655.65,3340.47 3708.21,3393.03 3893.03,3393.03 3910.98,3410.98 3910.98,3444.73 3944.87,3478.62 U6.19
GPIO13: FPC1.10 U6.20 | length 803.7
  Top Layer w10: v1(3456.42,3472.05) 3642.95,3472.05 3694.41,3420.59 v1(3735.95,3420.59)
  Bottom Layer w10: FPC1.10 3442.96,3458.59 v1(3456.42,3472.05) ; v1(3735.95,3420.59) 3749.49,3407.05 3877.05,3407.05 3895,3425 3895,3461.14 U6.20
GPIO14: U6.21 U7.1 | length 1891.3
  Top Layer w10: v1(3769.48,3439.48) 3769.48,3398.75 3745.93,3375.19 3605.67,3375.19 3517.01,3286.53 3517.01,3267.48 3530.48,3254.02 3540.65,3254.02 3560.18,3234.49 4046.42,3234.49 4287.91,3475.98 4393.83,3475.98 4405.58,3464.24 4431.75,3464.24 4464.02,3496.5 4464.02,3644.02 v1(4510,3690)
  Bottom Layer w10: v1(3769.48,3439.48) 3810.49,3439.48 3827.38,3422.59 3846.42,3422.59 3859.89,3436.06 3859.89,3453.75 U6.21 ; U7.1 4505.24,3685.24 v1(4510,3690)
GPIO15: FPC2.3 U6.22 | length 491.5
  Top Layer w10: v1(3665,3277.01) 3665,3285 3691.97,3311.97 3815.53,3311.97 3836.9,3333.34 v1(3836.9,3445.59)
  Bottom Layer w10: v1(3665,3277.01) 3669.53,3272.48 FPC2.3 ; v1(3836.9,3445.59) 3836.9,3458.62 U6.22
GPIO16: FPC2.4 U6.23 | length 518.1
  Top Layer w10: v1(3630,3277.01) 3678.98,3325.98 3789.61,3325.98 3813.4,3349.77 v1(3813.4,3467.99)
  Bottom Layer w10: v1(3630,3277.01) 3649.84,3257.16 FPC2.4 ; v1(3813.4,3467.99) 3813.4,3471.76 3816.64,3475 3825.42,3475 U6.23
GPIO17: FPC2.5 U6.24 | length 566
  Top Layer w10: v1(3600,3277.01) 3600,3279.52 3660.48,3340 3770,3340 3799.38,3369.38 3799.38,3449.49 3790.41,3458.47 3790.41,3460.98 v1(3783.4,3467.99)
  Bottom Layer w10: v1(3600,3277.01) 3600,3274.49 3630.16,3244.34 FPC2.5 ; v1(3783.4,3467.99) 3783.4,3487.54 3848.58,3552.73 U6.24
K: CN1.8 R3.2 U4.3 | length 329.4
  Bottom Layer w10: CN1.8 3492.98,3670.19 3525.19,3670.19 3535,3680 3535,3922.91 U4.3 3533.57,3956.09 R3.2
VDD_SPI: C14.2 U6.18 | length 145.7
  Bottom Layer w10: C14.2 3925,3435.42 U6.18
pads on no net: ANT1.1 CN1.14 FPC2.2 FPC2.6 FPC2.8

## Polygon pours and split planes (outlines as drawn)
GND on Bottom Layer (solid, remove dead copper, pour order 4): 3000,4102.82 4495,4102.82 4495,3000 3000,3000
GND on Top Layer (solid, remove dead copper, pour order 0): 3016.1,4097.82 4493.73,4097.82 4493.73,3030.82 3016.1,3030.82
GND on Bottom Layer (solid, remove dead copper, pour order 6): 4370,4097.82 4768.07,4097.82 4768.07,3938.73 4370,3938.73
GND on Top Layer (solid, remove dead copper, pour order 2): 4370,4097.82 4768.07,4097.82 4768.07,3928.73 4370,3928.73

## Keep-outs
Board Outline Layer:
  circle w1: c4709.01,3200.19 r27.56
  circle w10: c4709.01,3200.19 r27.56
  circle w1: c3161.77,3999.4 r27.56
  circle w10: c3161.77,3999.4 r27.56
  region: 3225,3790 3323.43,3790 3323.43,3475.04 3225,3475.04
  region: 3684.21,3733.87 3801.13,3850.8 3895.78,3756.14 3778.86,3639.22
  region: 4440.75,3947.12 4498.84,3998.46 4498.84,4100 4100,4100 4100,3947.12
  lines w1: 3225,3475.04 3323.43,3475.04 3323.43,3790 3225,3790 3225,3475.04
  lines w7.87: 3016.1,3180.82 3016.1,4077.82 cw(c3036.1,4077.82) 3036.1,4097.82 4748.07,4097.82 cw(c4748.07,4077.82) 4768.07,4077.82 4768.07,3180.82 ; 3026.1,3030.82 4738.07,3030.82
  lines w7.9: 3016.1,3180.82 3016.1,3105.82 3016.1,3030.82 3026.1,3030.82 ; 4738.07,3030.82 4769.79,3030.82 4768.07,3180.82

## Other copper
Top Layer:
  region net ADC_VIN: 4166.16,3679.75 4166.16,3669.75 4165.04,3669.66 4163.91,3669.41 4161.68,3668.52 4159.58,3667.25 4157.76,3665.8 4157.76,3683.7 4159.58,3682.25 4161.68,3680.98 4163.91,3680.09 4165.04,3679.84
  region net GPIO4: 4517.88,3925 4517.88,3935 4519,3935.09 4520.13,3935.34 4522.37,3936.23 4524.46,3937.5 4526.29,3938.95 4526.29,3921.05 4524.46,3922.5 4522.37,3923.77 4520.13,3924.66 4519,3924.91
  region net GND: 4635.14,3951.93 4628.07,3944.86 4627.21,3945.59 4626.24,3946.21 4624.02,3947.16 4621.65,3947.74 4619.33,3948.01 4631.99,3960.67 4632.26,3958.35 4632.84,3955.98 4633.79,3953.76 4634.41,3952.79
  region net GND: 4659.6,3668.59 4649.6,3668.59 4649.51,3669.71 4649.26,3670.84 4648.37,3673.07 4647.1,3675.17 4645.65,3676.99 4663.55,3676.99 4662.1,3675.17 4660.83,3673.07 4659.94,3670.84 4659.69,3669.71
  region net GND: 4658.14,3413.94 4651.06,3406.86 4650.3,3407.51 4649.54,3407.9 4648.79,3408.1 4648.02,3408.16 4646.34,3408.06 4644.33,3408.01 4656.99,3420.67 4656.94,3418.66 4656.84,3416.98 4656.9,3416.21 4657.1,3415.46 4657.49,3414.7
  region net GPIO6: 3455.14,3586.93 3448.07,3579.86 3447.21,3580.59 3446.24,3581.21 3444.02,3582.16 3441.65,3582.74 3439.33,3583.01 3451.99,3595.67 3452.26,3593.35 3452.84,3590.98 3453.79,3588.76 3454.41,3587.79
  region net GPIO7: 3460.14,3621.93 3453.07,3614.86 3452.21,3615.59 3451.24,3616.21 3449.02,3617.16 3446.65,3617.74 3444.33,3618.01 3456.99,3630.67 3457.26,3628.35 3457.84,3625.98 3458.79,3623.76 3459.41,3622.79
  region net BL: 3467.43,3713.8 3460.36,3706.73 3459.5,3707.46 3458.52,3708.08 3456.31,3709.03 3453.94,3709.61 3451.62,3709.88 3464.28,3722.54 3464.54,3720.22 3465.13,3717.84 3466.07,3715.63 3466.7,3714.65
  region net DN1: 3288.59,3240 3288.59,3250 3289.71,3250.09 3290.84,3250.34 3293.07,3251.23 3295.17,3252.5 3296.99,3253.95 3296.99,3236.05 3295.17,3237.5 3293.07,3238.77 3290.84,3239.66 3289.71,3239.91
  region net DN1: 3155,3340.59 3145,3346.59 3144.88,3348.87 3144.55,3351.56 3144.08,3354.24 3143.53,3356.45 3159.8,3348.99 3158.77,3348.4 3157.83,3347.59 3157.01,3346.61 3156.32,3345.5 3155.76,3344.3 3155.34,3343.06 3155.09,3341.8
  region net GPIO5: 4408.59,3485 4408.59,3495 4409.71,3495.09 4410.84,3495.34 4413.07,3496.23 4415.17,3497.5 4416.99,3498.95 4416.99,3481.05 4415.17,3482.5 4413.07,3483.77 4410.84,3484.66 4409.71,3484.91
  region net GPIO5: 4236.41,3495 4236.41,3485 4235.29,3484.91 4234.16,3484.66 4231.93,3483.77 4229.83,3482.5 4228.01,3481.05 4228.01,3498.95 4229.83,3497.5 4231.93,3496.23 4234.16,3495.34 4235.29,3495.09
  region net GND: 3505.14,3736.93 3498.07,3729.86 3497.21,3730.59 3496.24,3731.21 3494.02,3732.16 3491.65,3732.74 3489.33,3733.01 3501.99,3745.67 3502.26,3743.35 3502.84,3740.98 3503.79,3738.76 3504.41,3737.79
  region net GND: 3532.87,3664.26 3542.87,3664.26 3542.96,3663.14 3543.21,3662.01 3544.11,3659.77 3545.37,3657.68 3546.82,3655.85 3528.92,3655.85 3530.37,3657.68 3531.64,3659.77 3532.53,3662.01 3532.78,3663.14
  region net GPIO0: 4122.5,3679.89 4112.5,3683.62 4112.25,3685.81 4111.59,3687.97 4110.65,3690.05 4109.58,3692.03 4127.09,3688.3 4125.4,3686.68 4123.93,3684.53 4122.89,3682.17 4122.6,3681
  region net GPIO0: 3156.41,3930 3156.41,3920 3155.29,3919.91 3154.16,3919.66 3151.93,3918.77 3149.83,3917.5 3148.01,3916.05 3148.01,3933.95 3149.83,3932.5 3151.93,3931.23 3154.16,3930.34 3155.29,3930.09
Bottom Layer:
  region net GND: 3204.4,3305 3160,3305 3159.4,3304.4 3159.4,3295.6 3204.4,3295.6
  region net GPIO4: 4516.25,3927.4 4519.83,3937.4 4522.03,3937.66 4524.18,3938.33 4526.26,3939.28 4528.24,3940.37 4524.66,3922.83 4523.03,3924.51 4520.89,3925.97 4518.53,3927.01 4517.36,3927.3
  region net GND: 4603.59,3955 4603.59,3965 4604.71,3965.09 4605.84,3965.34 4608.07,3966.23 4610.17,3967.5 4611.99,3968.95 4611.99,3951.05 4610.17,3952.5 4608.07,3953.77 4605.84,3954.66 4604.71,3954.91
  region net GND: 4639.46,3693.07 4646.53,3700.14 4647.39,3699.41 4648.36,3698.79 4650.58,3697.84 4652.95,3697.26 4655.27,3696.99 4642.61,3684.33 4642.34,3686.65 4641.76,3689.02 4640.81,3691.24 4640.19,3692.21
  region net GND: 4625.59,3420 4631.59,3430 4633.87,3430.12 4636.56,3430.45 4639.24,3430.92 4641.45,3431.47 4633.99,3415.2 4633.4,3416.23 4632.59,3417.17 4631.61,3417.99 4630.5,3418.68 4629.3,3419.24 4628.06,3419.66 4626.8,3419.91
  region net BL: 3448.99,3739.46 3458.99,3736.93 3459.27,3734.71 3460.02,3732.54 3461.07,3730.46 3462.28,3728.53 3444.56,3731.06 3446.18,3732.75 3447.6,3734.87 3448.61,3737.19 3448.89,3738.35
  region net 3V3: 3547.5,3463.62 3562.5,3463.62 3562.41,3461.23 3562.38,3459.09 3562.5,3458.09 3562.77,3457.12 3563.24,3456.16 3563.95,3455.21 3546.05,3455.21 3546.76,3456.16 3547.23,3457.12 3547.5,3458.09 3547.62,3459.09 3547.59,3461.23
  region net GPIO6: 4117.5,3448.91 4127.5,3448.91 4127.59,3447.79 4127.84,3446.66 4128.73,3444.43 4130,3442.33 4131.45,3440.51 4113.55,3440.51 4115,3442.33 4116.27,3444.43 4117.16,3446.66 4117.41,3447.79
  region net GPIO0: 3131.93,3909.86 3124.86,3916.93 3125.59,3917.79 3126.21,3918.76 3127.16,3920.98 3127.74,3923.35 3128.01,3925.67 3140.67,3913.01 3138.35,3912.74 3135.98,3912.16 3133.76,3911.21 3132.79,3910.59
  region net DN1: 3171.41,3365 3171.41,3355 3170.29,3354.91 3169.16,3354.66 3166.93,3353.77 3164.83,3352.5 3163.01,3351.05 3163.01,3368.95 3164.83,3367.5 3166.93,3366.23 3169.16,3365.34 3170.29,3365.09
  region net GPIO5: 4441.41,3495 4441.41,3485 4440.29,3484.91 4439.16,3484.66 4436.93,3483.77 4434.83,3482.5 4433.01,3481.05 4433.01,3498.95 4434.83,3497.5 4436.93,3496.23 4439.16,3495.34 4440.29,3495.09
  region net GPIO4: 4228.59,3507.99 4228.59,3517.99 4229.71,3518.08 4230.84,3518.33 4233.07,3519.23 4235.17,3520.49 4236.99,3521.94 4236.99,3504.04 4235.17,3505.49 4233.07,3506.76 4230.84,3507.65 4229.71,3507.9
  region net GND: 3757.74,3672.9 3771.88,3658.76 3770.07,3656.83 3768.46,3654.9 3765.85,3651.31 3764.06,3648.55 3763.11,3647.15 3746.13,3664.13 3747.52,3665.09 3750.29,3666.87 3753.87,3669.48 3755.8,3671.09
  region net GND: 3751.5,3638.38 3737.36,3652.52 3739.17,3654.46 3740.78,3656.39 3743.39,3659.97 3745.18,3662.74 3746.13,3664.13 3763.11,3647.15 3761.71,3646.2 3758.95,3644.41 3755.36,3641.8 3753.43,3640.19
  region net GND: 3640.86,3652.54 3660.86,3656.6 3660.75,3655.13 3660.47,3653.75 3659.89,3651.33 3659.82,3650.32 3660.04,3649.45 3660.67,3648.74 3661.83,3648.2 3646.55,3639.32 3646.74,3640.55 3646.75,3641.61 3646.6,3642.53 3646.31,3643.34 3645.43,3644.69 3644.29,3645.87 3643.07,3647.05 3641.97,3648.43 3641.52,3649.25 3641.17,3650.2 3640.95,3651.28
  region net GND: 3640.86,3703.11 3660.86,3703.11 3660.95,3700.47 3661.18,3697.96 3661.87,3693.58 3662.56,3690.36 3662.87,3688.7 3638.86,3688.7 3639.17,3690.36 3639.86,3693.58 3640.55,3697.96 3640.78,3700.47
  region net GND: 3660.86,3674.29 3640.86,3674.29 3640.78,3676.94 3640.55,3679.44 3639.86,3683.82 3639.17,3687.04 3638.86,3688.7 3662.87,3688.7 3662.56,3687.04 3661.87,3683.82 3661.18,3679.44 3660.95,3676.94
  region net GND: 3679.54,3766.18 3693.68,3752.04 3691.87,3750.11 3690.26,3748.18 3687.65,3744.59 3685.87,3741.83 3684.91,3740.43 3667.93,3757.41 3669.33,3758.37 3672.09,3760.15 3675.68,3762.76 3677.61,3764.37
  region net GND: 3673.3,3731.66 3659.16,3745.8 3660.97,3747.74 3662.58,3749.67 3665.19,3753.25 3666.98,3756.02 3667.93,3757.41 3684.91,3740.43 3683.52,3739.48 3680.75,3737.69 3677.17,3735.08 3675.24,3733.47
  region net GND: 3723.03,3781.39 3708.89,3795.53 3710.7,3797.47 3712.31,3799.4 3714.92,3802.98 3716.71,3805.75 3717.66,3807.14 3734.64,3790.16 3733.25,3789.21 3730.48,3787.42 3726.9,3784.81 3724.97,3783.2
  region net GND: 3729.27,3815.91 3743.41,3801.77 3741.6,3799.84 3739.99,3797.91 3737.38,3794.32 3735.6,3791.56 3734.64,3790.16 3717.66,3807.14 3719.06,3808.1 3721.82,3809.88 3725.41,3812.49 3727.34,3814.1
  region net GND: 3785.91,3860 3789.55,3840 3788.06,3840.12 3786.66,3840.4 3784.2,3840.99 3783.18,3841.07 3782.32,3840.84 3781.63,3840.2 3781.15,3839.03 3771.54,3853.86 3772.88,3853.71 3774.05,3853.74 3775.05,3853.94 3775.93,3854.26 3777.41,3855.22 3778.68,3856.44 3779.96,3857.71 3781.45,3858.86 3782.34,3859.32 3783.36,3859.68 3784.54,3859.92
  region net GND: 3766.4,3824.76 3752.26,3838.9 3754.07,3840.83 3755.68,3842.76 3758.29,3846.35 3760.08,3849.11 3761.03,3850.51 3778.01,3833.53 3776.61,3832.58 3773.85,3830.79 3770.26,3828.18 3768.33,3826.57
  region net GND: 3784.66,3833.95 3777.59,3826.88 3776.73,3827.61 3775.75,3828.23 3773.54,3829.18 3771.17,3829.76 3768.85,3830.03 3781.51,3842.69 3781.78,3840.37 3782.36,3838 3783.31,3835.78 3783.93,3834.81
  region net GND: 3806.14,3840 3806.14,3860 3808.78,3860.09 3811.29,3860.31 3815.67,3861 3818.89,3861.69 3820.55,3862.01 3820.55,3837.99 3818.89,3838.31 3815.67,3839 3811.29,3839.69 3808.78,3839.91
  region net GND: 3834.96,3860 3834.96,3840 3832.31,3839.91 3829.81,3839.69 3825.43,3839 3822.21,3838.31 3820.55,3837.99 3820.55,3862.01 3822.21,3861.69 3825.43,3861 3829.81,3860.31 3832.31,3860.09
  region net GND: 3888.8,3846.99 3888.8,3861.99 3891.19,3861.9 3893.33,3861.86 3894.33,3861.99 3895.3,3862.26 3896.26,3862.73 3897.2,3863.44 3897.2,3845.54 3896.26,3846.25 3895.3,3846.72 3894.33,3846.99 3893.33,3847.11 3891.19,3847.08
  region net GND: 4349.55,3904.39 4326.92,3910.04 4328.12,3911.05 4329.4,3911.91 4331.74,3913.34 4332.56,3914.04 4332.99,3914.79 4332.89,3915.66 4332.16,3916.69 4349.83,3917.05 4349.19,3916.18 4348.8,3915.33 4348.63,3914.5 4348.65,3913.7 4349.08,3912.14 4349.8,3910.62 4350.5,3909.11 4350.9,3907.59 4350.88,3906.81 4350.68,3906.02 4350.25,3905.22
  region net GND: 4355.24,3935 4355.24,3915 4352.59,3914.91 4350.09,3914.69 4345.71,3914 4342.49,3913.31 4340.83,3912.99 4340.83,3937.01 4342.49,3936.69 4345.71,3936 4350.09,3935.31 4352.59,3935.09
  region net GND: 4387.76,3935 4387.76,3915 4385.12,3914.91 4382.61,3914.69 4378.23,3914 4375.01,3913.31 4373.35,3912.99 4373.35,3937.01 4375.01,3936.69 4378.23,3936 4382.61,3935.31 4385.12,3935.09
  region net GND: 4358.95,3915 4358.95,3935 4361.59,3935.09 4364.1,3935.31 4368.48,3936 4371.69,3936.69 4373.35,3937.01 4373.35,3912.99 4371.69,3913.31 4368.48,3914 4364.1,3914.69 4361.59,3914.91
  region net GND: 4320.69,3875.52 4314.91,3898.03 4315.67,3898.66 4316.41,3899.05 4317.14,3899.23 4317.86,3899.23 4319.28,3898.86 4320.69,3898.2 4322.09,3897.56 4323.5,3897.19 4324.22,3897.19 4324.94,3897.38 4325.68,3897.77 4326.43,3898.41 4327.33,3880.76 4326.25,3881.42 4325.36,3881.47 4324.6,3881.04 4323.91,3880.24 4322.51,3877.95 4321.68,3876.7
  region net GND: 4326.97,3910.09 4349.48,3904.31 4348.3,3903.32 4347.05,3902.49 4344.76,3901.09 4343.96,3900.4 4343.53,3899.64 4343.58,3898.75 4344.24,3897.67 4326.59,3898.57 4327.23,3899.32 4327.62,3900.06 4327.81,3900.78 4327.81,3901.5 4327.44,3902.91 4326.8,3904.31 4326.14,3905.72 4325.77,3907.14 4325.77,3907.86 4325.95,3908.59 4326.34,3909.33
  region net GND: 4483.22,3958.49 4470.47,3974.03 4471.46,3974.71 4472.64,3975.12 4475.25,3975.53 4476.47,3975.75 4477.52,3976.11 4478.29,3976.73 4478.69,3977.7 4489.71,3963.89 4488.44,3963.85 4487.45,3963.54 4486.68,3963.02 4486.04,3962.32 4484.84,3960.53 4484.12,3959.52
  region net GND: 4492.39,3995.95 4507.65,3982.93 4505.72,3981.38 4504.03,3980.22 4503.36,3979.6 4502.86,3978.86 4502.58,3977.92 4502.54,3976.71 4488.72,3987.73 4489.7,3988.13 4490.31,3988.9 4490.68,3989.95 4490.89,3991.18 4491.31,3993.78 4491.71,3994.97
  region net GND: 4455.72,3959.28 4469.86,3945.14 4468.05,3943.2 4466.44,3941.27 4463.83,3937.69 4462.04,3934.92 4461.09,3933.53 4444.11,3950.51 4445.5,3951.46 4448.27,3953.25 4451.85,3955.86 4453.79,3957.47
  region net GND: 4467.39,3928.22 4453.24,3921.15 4451.7,3922.88 4450.67,3924.41 4449.43,3927.1 4448.85,3928.36 4448.07,3929.66 4446.91,3931.04 4445.19,3932.57 4462.5,3935.22 4461.93,3934.08 4461.89,3933.12 4462.28,3932.29 4463,3931.54 4465.09,3930.06 4466.26,3929.21
  region net GND: 4498.49,3973.76 4487.57,3991.13 4488.41,3991.86 4489.25,3992.4 4490.9,3992.98 4492.51,3993.11 4494.06,3993.06 4495.55,3993.05 4496.95,3993.34 4497.62,3993.67 4498.27,3994.17 4498.89,3994.87 4499.48,3995.79 4505.1,3979.04 4503.88,3979.4 4502.92,3979.31 4502.14,3978.84 4501.48,3978.08 4500.2,3976.02 4499.44,3974.87
  region net GND: 4468.06,3943.34 4453.06,3956.62 4454.71,3958.4 4455.86,3959.92 4457.34,3962.54 4458.77,3965.21 4459.86,3966.79 4461.41,3968.65 4479.23,3952.55 4477.57,3950.82 4476.16,3949.56 4473.75,3947.85 4471.28,3946.18 4469.81,3944.98
  region net GND: 4478.54,3982.1 4491.83,3967.1 4489.48,3964.65 4487.74,3962.61 4485.23,3959.26 4482.66,3955.97 4480.83,3954.02 4478.37,3951.69 4462.27,3969.51 4464.86,3971.73 4467.01,3973.36 4470.54,3975.66 4474.01,3978.04 4476.07,3979.76
  region net GND: 3135.06,3662.98 3142.14,3670.06 3142.99,3669.32 3143.97,3668.7 3146.18,3667.76 3148.55,3667.17 3150.87,3666.9 3138.21,3654.25 3137.95,3656.57 3137.36,3658.94 3136.42,3661.15 3135.79,3662.13
  region net GND: 3497.16,3730.33 3487.16,3727.11 3487.06,3728.22 3486.78,3729.38 3485.75,3731.73 3484.3,3733.86 3482.64,3735.51 3500.25,3738.74 3499.12,3736.78 3498.13,3734.7 3497.43,3732.54
  region net GND: 3364.01,3579.89 3357.83,3569.89 3355.72,3569.71 3353.56,3569.25 3351.43,3568.61 3349.43,3567.86 3355.6,3584.67 3356.24,3583.72 3357.08,3582.83 3358.09,3582.02 3359.22,3581.31 3361.65,3580.27 3362.86,3579.98
  region net GND: 3340,3595.44 3350,3595.44 3350.09,3594.32 3350.34,3593.18 3351.23,3590.95 3352.5,3588.86 3353.95,3587.03 3336.05,3587.03 3337.5,3588.86 3338.77,3590.95 3339.66,3593.18 3339.91,3594.32
  region net GND: 4620.43,3430 cw(c4620.43,3496.61) 4575.43,3447.5 4567.93,3425
  region net GND: 3492.16,3585.64 ccw(c3492.16,3539.29) 3470.2,3580.1 3465.2,3590.64 3470.2,3601.58 ccw(c3492.16,3639.18) 3492.16,3595.64
  region net GND: 3492.16,3564.14 cw(c3492.16,3592.48) 3469.94,3574.89 3459.94,3574.89 cw(c3429.94,3615.47) 3429.94,3565 3429.94,3555 cw(c3429.94,3504.77) 3459.94,3545.06 3469.94,3545.06 cw(c3492.16,3522.39) 3492.16,3554.14
  region net 3V3: 4381.46,3618.54 4388.54,3611.46 ccw(c4473.15,3526.85) 4376.53,3597.44 4369.62,3609.52 ccw(c4342.3,3657.7)
  region net 3V3: 4402.04,3582.6 4405,3572.6 ccw(c4405,3471.6) 4385,3570.6 4382.04,3584.15 ccw(c4402.04,3712.24)
  region net 3V3: 3532.54,3592.5 3540.25,3602.5 ccw(c3555.32,30628.81) 3555.25,3602.5 3547.5,3592.25 ccw(c3532.54,3144.77)
  region net GND: 4503.17,3607.93 ccw(c4503.17,3580.35) 4477.5,3590.43 4470,3612.93
  region net GND: 4420,3700 ccw(c4420,3760.36) 4462.5,3717.5 4470,3692.58 4462.5,3672.5 ccw(c4420,3629.64) 4420,3690
  region net GND: 3155,3270.27 3165,3270.27 ccw(c3182.65,3270.27) 3172.5,3255.82 3147.5,3255.82 ccw(c3137.35,3270.27)
  region net 3V3: 3177.59,3436.7 3177.59,3446.7 ccw(c3192.59,3505.12) 3192.59,3444.8 3192.59,3432.99 ccw(c3177.59,3404.48)
  region net DN1: 3177.59,3355 3177.59,3365 ccw(c3177.59,3471.61) 3192.59,3366.06 3192.59,3354.25 ccw(c3177.59,3204.72)
  region net GND: 3188.04,3293.3 3188.04,3303.3 ccw(c3188.04,3307.95) 3192.59,3307.01 3192.59,3295.2 ccw(c3192.59,3288.79)
  region net GND: 3761.69,3648.57 3747.55,3662.71 ccw(c3735.16,3675.1) 3749.2,3685.58 3780.25,3654.52 ccw(c3776.75,3633.51)
  region net GND: 3773.76,3830.71 3780.83,3837.78 ccw(c3794.09,3851.04) 3796.74,3832.47 3779.06,3814.8 ccw(c3760.5,3817.45)
  region net $1N1185: 3882.87,3735.92 3875.8,3728.85 ccw(c3862.54,3715.59) 3859.89,3734.15 3877.57,3751.83 ccw(c3896.13,3749.18)
  region net $1N1185: 3874.17,3782.27 3881.24,3775.2 ccw(c3894.5,3761.94) 3875.94,3759.29 3858.26,3776.96 ccw(c3860.91,3795.52)
  region net $1N1184: 3771.46,3753.54 3778.54,3746.46 ccw(c3810.16,3702.57) 3771.9,3740.82 3760.02,3752.7 ccw(c3765.26,3759.74)
  region net $1N1184: 3720.83,3692.73 3713.76,3699.8 ccw(c3700.5,3713.06) 3719.06,3715.71 3732.93,3701.85 ccw(c3759.27,3654.29)
  region net GND: 4373.35,3915 4373.35,3935 ccw(c4373.35,3965.12) 4393.66,3942.87 4393.66,3921.93 ccw(c4393.66,3888.71)
  region net GND: 4442.98,3939.9 4442.98,3924.9 ccw(c4442.98,3914.89) 4435.86,3921.93 4435.86,3942.87 ccw(c4442.98,3949.91)
  region net 3V3: 4445.2,3862.6 4445.2,3852.6 ccw(c4445.2,3841.9) 4435.86,3847.13 4435.86,3868.07 ccw(c4445.2,3873.3)
  region net 3V3: 4403.47,3839.24 4384.83,3834.74 ccw(c4352.33,3867.24) 4393.66,3847.13 4416.79,3847.13 ccw(c4425.55,3817.16)
  region net $1N1977: 4541.34,3865.9 4541.34,3855.9 ccw(c4541.34,3837.15) 4526.34,3848.4 4526.34,3868.07 ccw(c4541.34,3918.71)
  region net GND: 4471.09,3903.3 4482.18,3913.43 ccw(c4506.04,3945.25) 4506.04,3905.47 4484.14,3884.53 ccw(c4425.47,3857.68)
  region net GND: 4541.34,3900 4541.34,3890 ccw(c4541.34,3866.71) 4526.34,3884.53 4526.34,3905.47 ccw(c4541.34,3923.29)
  region net GPIO4: 4531.89,3937.4 4531.89,3927.4 ccw(c4531.89,3921.85) 4526.34,3921.93 4526.34,3942.87 ccw(c4531.89,3942.95)
  region net GND: 4409.76,3677.87 4419.76,3677.87 ccw(c4438.51,3677.87) 4427.26,3662.87 4402.26,3662.87 ccw(c4391.01,3677.87)
  region net 3V3: 4385,3610 4385,3620 ccw(c4385,3629.58) 4393.66,3625.47 4393.66,3604.53 ccw(c4385,3600.42)
  region net 3V3: 4378.66,3572.6 4378.66,3582.6 ccw(c4378.66,3605.89) 4393.66,3588.07 4393.66,3567.13 ccw(c4378.66,3549.31)
  region net $1N1981: 4541.34,3582.6 4541.34,3572.6 ccw(c4541.34,3549.31) 4526.34,3567.13 4526.34,3588.07 ccw(c4541.34,3605.89)
  region net GND: 4541.34,3620 4541.34,3610 ccw(c4541.34,3586.71) 4526.34,3604.53 4526.34,3625.47 ccw(c4541.34,3643.29)
  region net GND: 4477.07,3607.93 4477.07,3617.93 ccw(c4476.62,3625.43) 4484.14,3625.43 4484.14,3604.53 ccw(c4477.07,3598.89)
  region net GND: 4445,3379.9 4445,3364.9 ccw(c4445,3349.37) 4435.86,3361.93 4435.86,3382.87 ccw(c4445,3395.43)
  region net 3V3: 4375,3325 4375,3345 ccw(c4375,3713.6) 4393.66,3345.47 4393.66,3324.53 ccw(c4375,2956.4)
  region net 3V3: 4364.65,3287.6 4364.65,3307.6 ccw(c4364.65,4198.45) 4393.66,3308.07 4393.66,3287.13 ccw(c4364.65,2396.75)
  region net $1N1980: 4541.34,3302.6 4541.34,3292.6 ccw(c4541.34,3269.31) 4526.34,3287.13 4526.34,3308.07 ccw(c4541.34,3325.89)
  region net GND: 4542.44,3342.5 4542.44,3327.5 ccw(c4542.44,3282.43) 4526.34,3324.53 4526.34,3345.47 ccw(c4542.44,3387.57)
  region net GND: 4482.4,3327.5 4482.4,3342.5 ccw(c4480.73,3345.47) 4484.14,3345.47 4484.14,3324.53 ccw(c4480.73,3324.53)
  region net GPIO5: 4500.24,3397.87 4510.24,3397.87 ccw(c4528.99,3397.87) 4517.74,3382.87 4492.74,3382.87 ccw(c4481.49,3397.87)
  region net 3V3: 3953.54,3709.39 3960.61,3716.46 3963.41,3713.37 3965.59,3710.56 3967.99,3707.24 3960.2,3699.45 3959.44,3700.71 3958.16,3703.13 3956.23,3706.19 3954.99,3707.8
  region net 3V3: 3990.77,3444.32 3983.69,3437.25 3979.75,3441.09 3977.79,3442.72 3975.84,3443.98 3973.89,3444.74 3972.92,3444.9 3971.94,3444.88 3970.96,3444.67 3969.97,3444.26 3968.99,3443.63 3967.99,3442.76 3985.25,3460.02 3984.38,3459.03 3983.75,3458.04 3983.34,3457.06 3983.13,3456.07 3983.11,3455.1 3983.27,3454.12 3984.03,3452.17 3985.29,3450.22 3986.92,3448.26
  region net $1N1223: 4046.89,3703.54 4053.96,3696.46 4047.12,3689.27 4043.73,3685.52 4035.94,3693.31 4039.69,3696.7
  region net 3V3: 3427.01,3959.66 3427.01,3949.66 ccw(c3427.01,3930.91) 3412.01,3942.16 3412.01,3967.16 ccw(c3427.01,3978.41)
  region net 3V3: 3363.82,3931.75 3372.62,3954.69 ccw(c3351.94,3970.54) 3377.99,3970.54 3377.99,3938.78 ccw(c3381.37,3914.2)
  region net $1N1544: 3427.01,3900.34 3427.01,3890.34 ccw(c3427.01,3871.59) 3412.01,3882.84 3412.01,3907.84 ccw(c3427.01,3919.09)
  region net $1N1544: 3400,3864.46 3390,3864.46 ccw(c3371.25,3864.46) 3382.5,3879.46 3407.5,3879.46 ccw(c3418.75,3864.46)
  region net GND: 3120.12,3690 3120.12,3680 3118.8,3679.83 3117.65,3679.35 3116.64,3678.59 3115.75,3677.59 3114.96,3676.38 3114.25,3675 3113,3671.9 3111.84,3668.56 3110.61,3665.28 3109.15,3662.35 3108.29,3661.1 3107.31,3660.06 3107.31,3709.94 3108.29,3708.9 3109.15,3707.65 3110.61,3704.72 3111.84,3701.44 3113,3698.1 3114.25,3695 3114.96,3693.62 3115.75,3692.41 3116.64,3691.41 3117.65,3690.65 3118.8,3690.17
  region net GPIO0: 3080,3833.46 3090,3833.46 ccw(c3108.75,3833.46) 3097.5,3818.46 3072.5,3818.46 ccw(c3061.25,3833.46)
  region net GND: 3487.16,3735.55 3497.16,3735.55 ccw(c3515.91,3735.55) 3504.66,3720.55 3479.66,3720.55 ccw(c3468.41,3735.55)
  region net 3V3: 3990,3368.31 4000,3368.31 ccw(c4018.75,3368.31) 4007.5,3353.31 3982.5,3353.31 ccw(c3971.25,3368.31)
  region net $1N1223: 4173.65,3758.22 4184.26,3747.62 ccw(c4208.88,3722.99) 4174.18,3725.88 4151.9,3748.15 ccw(c4149.04,3782.83)
  region net $1N1223: 4121.71,3716.99 4124.49,3731.99 ccw(c4118.87,3771.36) 4146.99,3743.24 4144.21,3705.74 ccw(c4116.08,3677.61)
  region net 3V3: 3976.59,3879.68 3983.66,3872.61 ccw(c3997.24,3859.03) 3978.15,3856.9 3960.68,3874.38 ccw(c3963.33,3892.94)
  region net $1N1219: 4166.31,3983.78 4155.21,3987.87 ccw(c4136.62,4011.65) 4166.14,4005.35 4195.02,3994.72 ccw(c4199.54,3939.73)
  region net GND: 3922.09,3848.01 3911.34,3837.56 3909.72,3839.31 3908.24,3840.85 3907.45,3841.47 3906.58,3841.98 3905.58,3842.33 3904.4,3842.51 3917.21,3855.02 3917.36,3853.84 3917.7,3852.83 3918.19,3851.95 3918.81,3851.15 3920.34,3849.64
  region net GND: 3928.16,3820.74 3938.76,3831.34 3940.39,3829.59 3941.88,3828.06 3942.67,3827.43 3943.55,3826.94 3944.56,3826.59 3945.73,3826.43 3933.07,3813.77 3932.91,3814.94 3932.56,3815.95 3932.07,3816.83 3931.44,3817.62 3929.91,3819.11
  region net 3V3: 4354.65,3324.65 cw(c4334.65,3327.86) 4334.65,3307.6 4364.65,3297.6 4394.65,3307.6 cw(c4394.65,3327.86) 4374.65,3324.65

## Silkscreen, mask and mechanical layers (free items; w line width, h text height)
Mechanical Layer:
  circle w1: c4709.01,3200.19 r27.56
  circle w1: c3161.77,3999.4 r27.56
  lines w1: 3225,3475.04 3323.43,3475.04 3323.43,3790 3225,3790 3225,3475.04
Mech6:
  circle w7.87: c4709.01,3349.79 r7.87
  circle w7.87: c4709.01,3625.38 r7.87
  circle w7.87: c4709.01,3900.97 r7.87
  lines w0.2: 3335,3096.38 4476.73,3096.38 4476.73,4120 3335,4120 3335,3096.38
